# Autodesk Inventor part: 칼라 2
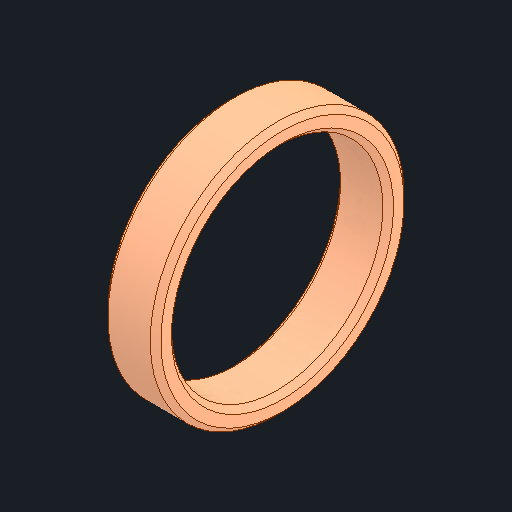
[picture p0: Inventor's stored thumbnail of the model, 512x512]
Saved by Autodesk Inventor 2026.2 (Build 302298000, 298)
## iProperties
Created: 2025-11
Part Number: 칼라 2
Material: 강철, 연강
Document SubType Name: Modeling
Designer: PC2-07
Density: 7.85 g/cm^3
Appearance: 기본값
Author: jhkim
Sending System: Autodesk Inventor 2026
Preprocessor: ST-DEVELOPER v20.1
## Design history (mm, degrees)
feature "솔리드1"
node "솔리드2"
